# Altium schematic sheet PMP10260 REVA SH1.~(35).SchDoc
size 431 x 279 mm; Date: Not shown in title block; ApprovedBy: Not shown in title block; CheckedBy: Not shown in title block; Author: Not shown in title block; CompanyName: Not shown in title block; Engineer: Not shown in title block; Organization: Not shown in title block; Address1: Not shown in title block; Address2: Not shown in title block; Address3: Not shown in title block; Address4: Not shown in title block; DocumentNumber: 1; Revision: Use project parameter SCH_Rev; SheetNumber: 1; SheetTotal: 4; PageSetup: Record=PageOptions|CenterHorizontal=True|CenterVertical=True|PrintScale=1.00|XCorrection=1.00|YCorrection=1.00|PrintKind=0|BorderSize=5000000|LeftOffset=0|BottomOffset=0|Orientation=2|PaperLength=1000|PaperWidth=1000|Scale=100|PaperSource=15|PrintQuality=600|MediaType=1|DitherType=10|PaperKind=Letter|PrintScaleMode=1
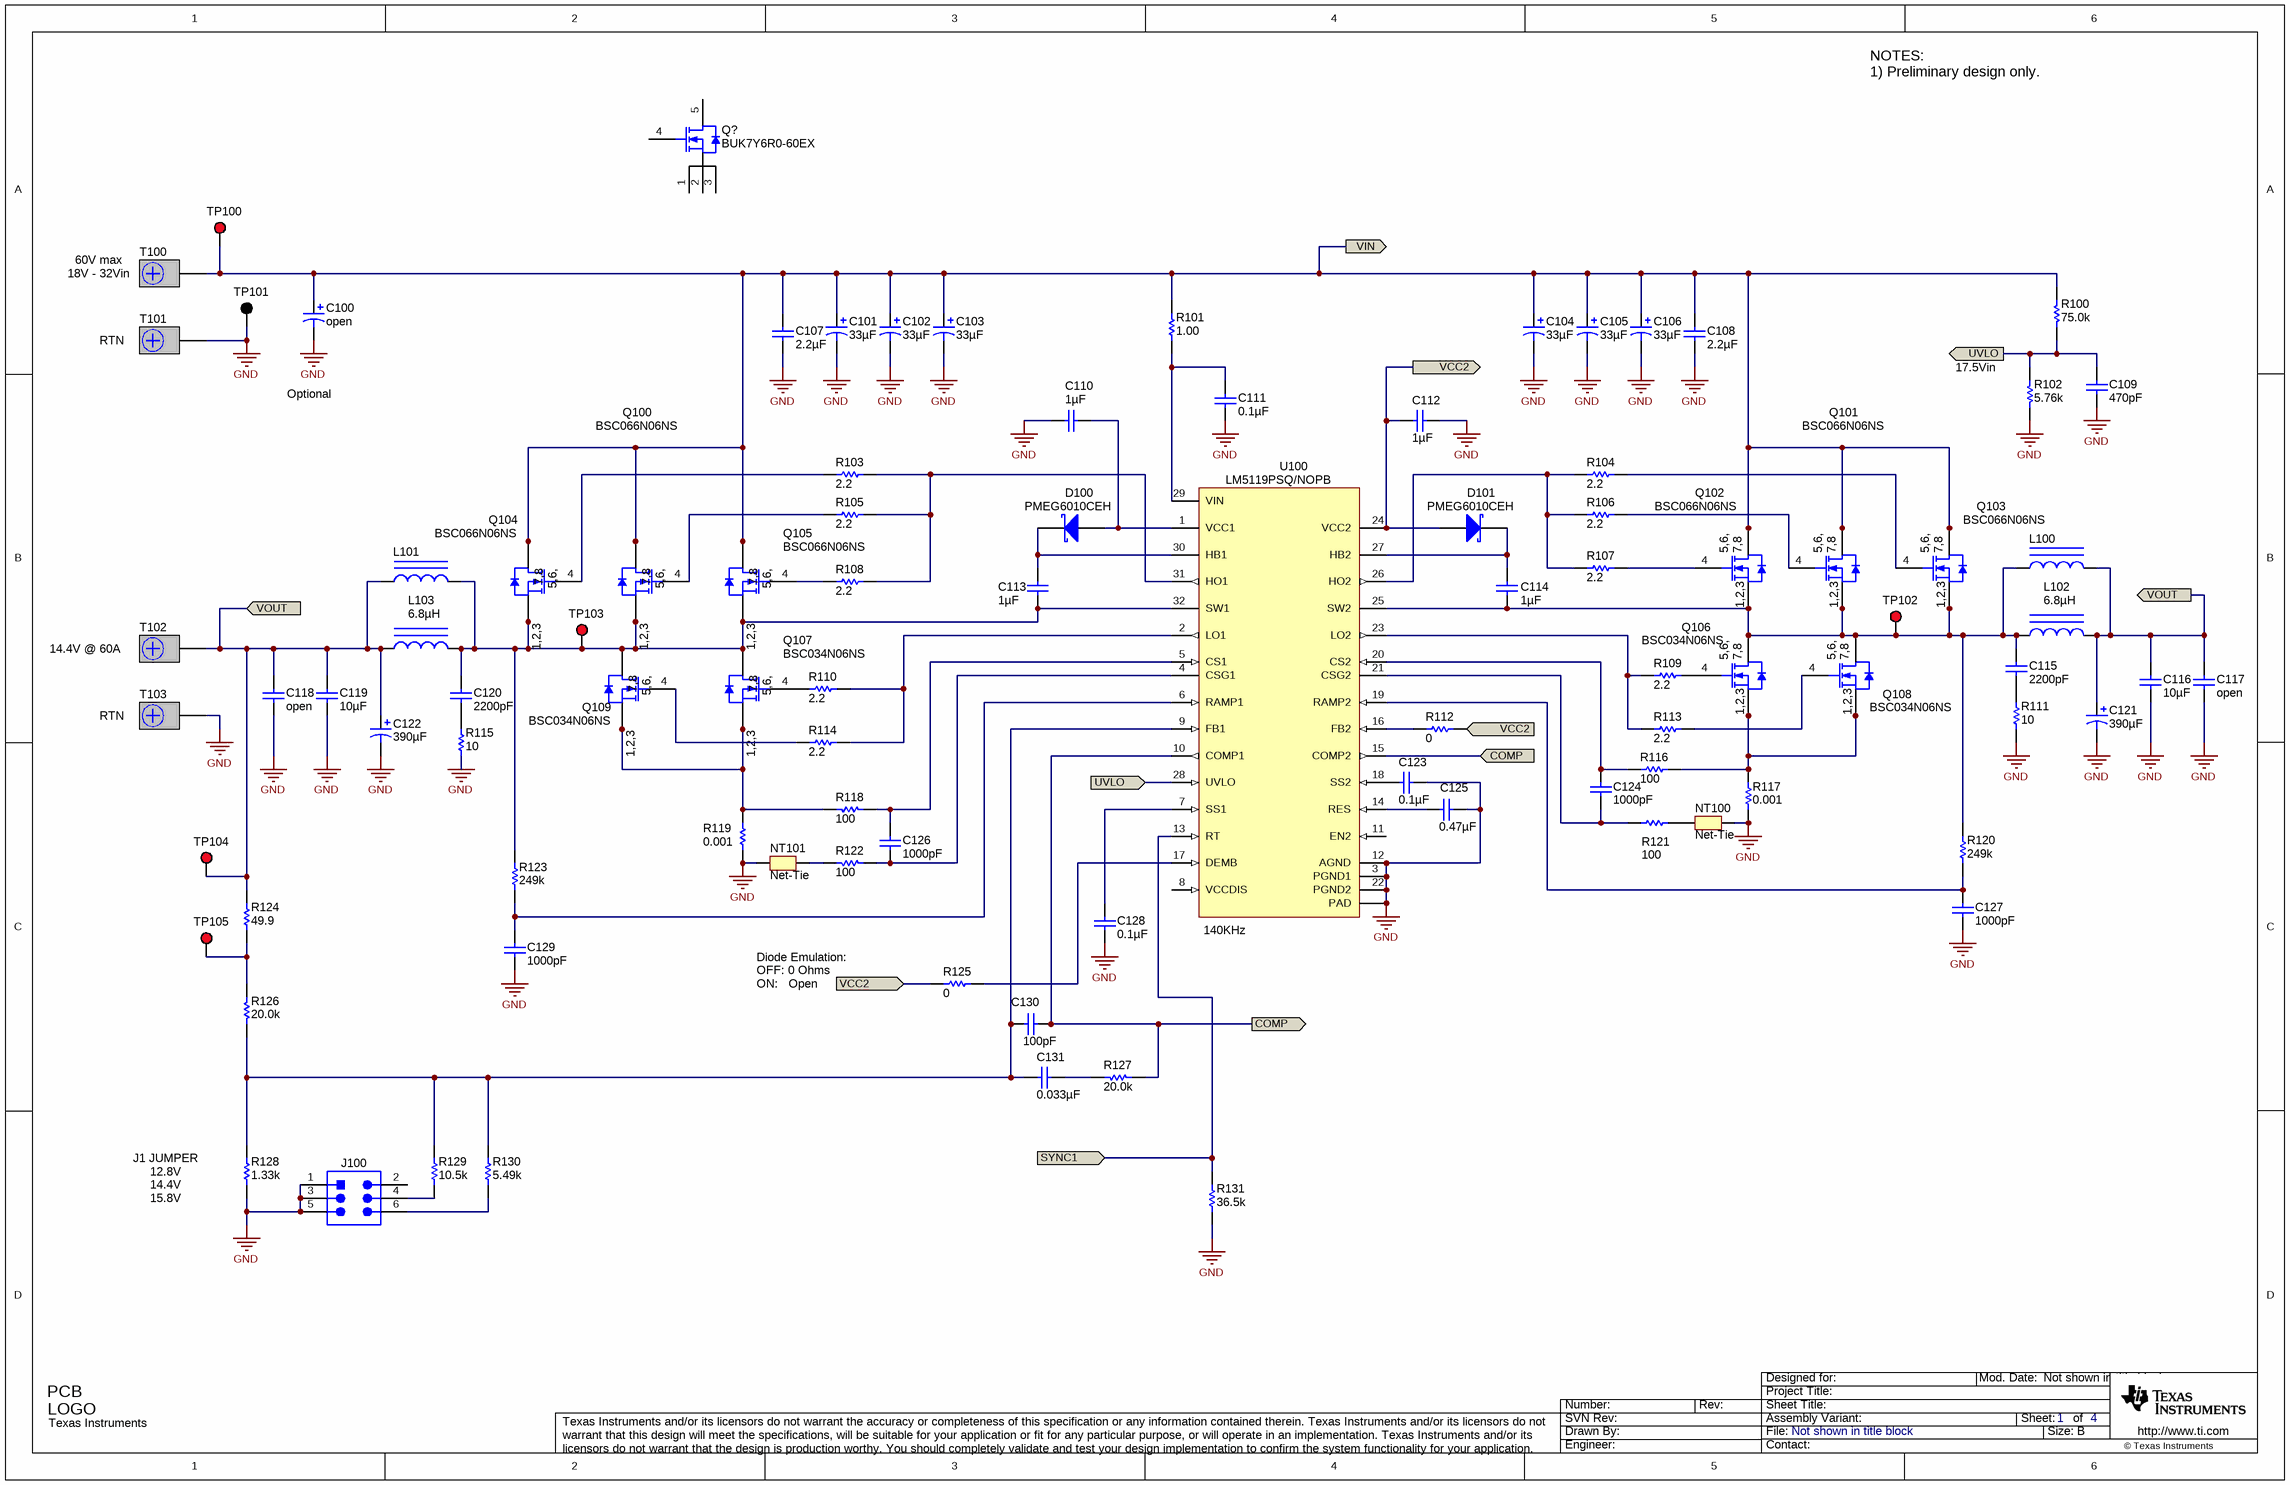
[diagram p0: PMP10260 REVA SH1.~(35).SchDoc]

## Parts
C100  ValueDisplayed: open  [SM_RADIAL_8MM]
C101  ValueDisplayed: 33µF  [SXV_E12]  (hidden comment: 63SXV33M)
C102  ValueDisplayed: 33µF  [SXV_E12]  (hidden comment: 63SXV33M)
C103  ValueDisplayed: 33µF  [SXV_E12]  (hidden comment: 63SXV33M)
C104  ValueDisplayed: 33µF  [SXV_E12]  (hidden comment: 63SXV33M)
C105  ValueDisplayed: 33µF  [SXV_E12]  (hidden comment: 63SXV33M)
C106  ValueDisplayed: 33µF  [SXV_E12]  (hidden comment: 63SXV33M)
C107  ValueDisplayed: 2.2µF  [1210]  (hidden comment: GRM32ER72A225KA35L)
C108  ValueDisplayed: 2.2µF  [1210]  (hidden comment: GRM32ER72A225KA35L)
C109  ValueDisplayed: 470pF  [0603]  (hidden comment: C1608C0G1H471J)
C110  ValueDisplayed: 1µF  [0603L]  (hidden comment: C1608X7R1E105K080AB)
C111  ValueDisplayed: 0.1µF  [0805_HV]  (hidden comment: C2012X7R2A104K)
C112  ValueDisplayed: 1µF  [0603L]  (hidden comment: C1608X7R1E105K080AB)
C113  ValueDisplayed: 1µF  [0603L]  (hidden comment: C1608X7R1E105K080AB)
C114  ValueDisplayed: 1µF  [0603L]  (hidden comment: C1608X7R1E105K080AB)
C115  ValueDisplayed: 2200pF  [0603L]  (hidden comment: C0603C222K5RAC)
C116  ValueDisplayed: 10µF  [1210L]  (hidden comment: GMK325AB7106MM-T)
C117  ValueDisplayed: open  [1210]
C118  ValueDisplayed: open  [1210]
C119  ValueDisplayed: 10µF  [1210L]  (hidden comment: GMK325AB7106MM-T)
C120  ValueDisplayed: 2200pF  [0603L]  (hidden comment: C0603C222K5RAC)
C121  ValueDisplayed: 390µF  [SM_RADIAL_8MM]  (hidden comment: 20SVPF390M)
C122  ValueDisplayed: 390µF  [SM_RADIAL_8MM]  (hidden comment: 20SVPF390M)
C123  ValueDisplayed: 0.1µF  [0603L]  (hidden comment: C1608X7R1H104K)
C124  ValueDisplayed: 1000pF  [0603]  (hidden comment: C1608C0G1H102J)
C125  ValueDisplayed: 0.47µF  [0603L]  (hidden comment: C0603C474K4RACTU)
C126  ValueDisplayed: 1000pF  [0603]  (hidden comment: C1608C0G1H102J)
C127  ValueDisplayed: 1000pF  [0603]  (hidden comment: C1608C0G1H102J)
C128  ValueDisplayed: 0.1µF  [0603L]  (hidden comment: C1608X7R1H104K)
C129  ValueDisplayed: 1000pF  [0603]  (hidden comment: C1608C0G1H102J)
C130  ValueDisplayed: 100pF  [0603]  (hidden comment: C1608C0G1H101J)
C131  ValueDisplayed: 0.033µF  [0603]  (hidden comment: GRM188R71H333KA61D)
D100  PMEG6010CEH  [SOD-123F]
D101  PMEG6010CEH  [SOD-123F]
J100  PEC03DAAN  [SULLINS_PEC03DAAN]  (value not drawn)
L100  (no value)  [XAL1510]
L101  (no value)  [XAL1510]
L102  ValueDisplayed: 6.8µH  [SER2915]  (hidden comment: SER2915H-682KL)
L103  ValueDisplayed: 6.8µH  [SER2915]  (hidden comment: SER2915H-682KL)
Logo100  Texas Instruments  [TI_Stacked_Overlay_Small]  (no BOM)
NT100  Net-Tie  [Net-Tie_10mil]  (net tie, no BOM)
NT101  Net-Tie  [Net-Tie_10mil]  (net tie, no BOM)
Q100  BSC066N06NS  [PG-TDSON-8]
Q101  BSC066N06NS  [PG-TDSON-8]
Q102  BSC066N06NS  [PG-TDSON-8]
Q103  BSC066N06NS  [PG-TDSON-8]
Q104  BSC066N06NS  [PG-TDSON-8]
Q105  BSC066N06NS  [PG-TDSON-8]
Q106  BSC034N06NS  [PG-TDSON-8]
Q107  BSC034N06NS  [PG-TDSON-8]
Q108  BSC034N06NS  [PG-TDSON-8]
Q109  BSC034N06NS  [PG-TDSON-8]
Q?  BUK7Y6R0-60EX  [LFPAK56]
R100  value 75.0k  [0603]  (hidden comment: CRCW060375K0FKEA)
R101  value 1.00  [0805_HV]  (hidden comment: CRCW08051R00FKEA)
R102  value 5.76k  [0603]  (hidden comment: CRCW06035K76FKEA)
R103  value 2.2  [0603L]  (hidden comment: CRCW06032R20JNEA)
R104  value 2.2  [0603L]  (hidden comment: CRCW06032R20JNEA)
R105  value 2.2  [0603L]  (hidden comment: CRCW06032R20JNEA)
R106  value 2.2  [0603L]  (hidden comment: CRCW06032R20JNEA)
R107  value 2.2  [0603L]  (hidden comment: CRCW06032R20JNEA)
R108  value 2.2  [0603L]  (hidden comment: CRCW06032R20JNEA)
R109  value 2.2  [0603L]  (hidden comment: CRCW06032R20JNEA)
R110  value 2.2  [0603L]  (hidden comment: CRCW06032R20JNEA)
R111  value 10  [2010M]  (hidden comment: CRCW201010R0JNEFHP)
R112  value 0  [0603L]  (hidden comment: CRCW06030000Z0EA)
R113  value 2.2  [0603L]  (hidden comment: CRCW06032R20JNEA)
R114  value 2.2  [0603L]  (hidden comment: CRCW06032R20JNEA)
R115  value 10  [2010M]  (hidden comment: CRCW201010R0JNEFHP)
R116  value 100  [0603L]  (hidden comment: RC0603FR-07100RL)
R117  value 0.001  [2512M]  (hidden comment: ERJ-M1WTF1M0U)
R118  value 100  [0603L]  (hidden comment: RC0603FR-07100RL)
R119  value 0.001  [2512M]  (hidden comment: ERJ-M1WTF1M0U)
R120  value 249k  [0603]  (hidden comment: CRCW0603249KFKEA)
R121  value 100  [0603L]  (hidden comment: RC0603FR-07100RL)
R122  value 100  [0603L]  (hidden comment: RC0603FR-07100RL)
R123  value 249k  [0603]  (hidden comment: CRCW0603249KFKEA)
R124  value 49.9  [0603]  (hidden comment: CRCW060349R9FKEA)
R125  value 0  [0603L]  (hidden comment: CRCW06030000Z0EA)
R126  value 20.0k  [0603L]  (hidden comment: CRCW060320K0FKEA)
R127  value 20.0k  [0603]  (hidden comment: CRCW060320K0FKEA)
R128  value 1.33k  [0603]  (hidden comment: CRCW06031K33FKEA)
R129  value 10.5k  [0603]  (hidden comment: CRCW060310K5FKEA)
R130  value 5.49k  [0603]  (hidden comment: CRCW06035K49FKEA)
R131  value 36.5k  [0603]  (hidden comment: CRCW060336K5FKEA)
T100  CB35-36-CY  [CB35-36-CY]  (value not drawn)
T101  CB35-36-CY  [CB35-36-CY]  (value not drawn)
T102  CB70-14-CY  [CB70-14-CY]  (value not drawn)
T103  CB70-14-CY  [CB70-14-CY]  (value not drawn)
TP100  5010  [Keystone5010]  (value not drawn)
TP101  5011  [Keystone5011]  (value not drawn)
TP102  5010  [Keystone5010]  (value not drawn)
TP103  5010  [Keystone5010]  (value not drawn)
TP104  5010  [Keystone5010]  (value not drawn)
TP105  5010  [Keystone5010]  (value not drawn)
U100  LM5119PSQ/NOPB  [RTV0032A]

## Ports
COMP, SYNC1, UVLO, VCC2, VIN, VOUT

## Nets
GND: C100.2(-) C101.2(-) C102.2(-) C103.2(-) C104.2(-) C105.2(-) C106.2(-) C107.2 C108.2 C109.2 C110.2 C111.2 C112.2 C116.2 C117.2 C118.2 C119.2 C121.2(-) C122.2(-) C123.1 C125.1 C127.2 C128.2 C129.2 J100.1 J100.3 J100.5 NT100.2 NT101.1 R102.1 R111.1 R115.1 R117.1 R119.1 R128.1 R131.1 T101.1 T103.1 TP101.1 U100.3(PGND1) U100.12(AGND) U100.22(PGND2) U100.33(PAD)
COMP: C130.1 R127.1 U100.10(COMP1) U100.15(COMP2) ; port COMP
SYNC1: R131.2 U100.13(RT) ; port SYNC1
UVLO: C109.1 R100.1 R102.2 U100.28(UVLO) ; port UVLO
VCC2: C112.1 D101.2(A) R112.2 R125.1 U100.24(VCC2) ; port VCC2
VIN: C100.1(+) C101.1(+) C102.1(+) C103.1(+) C104.1(+) C105.1(+) C106.1(+) C107.1 C108.1 Q100.5(D) Q100.6(D) Q100.7(D) Q100.8(D) Q100.9(D) Q101.5(D) Q101.6(D) Q101.7(D) Q101.8(D) Q101.9(D) Q102.5(D) Q102.6(D) Q102.7(D) Q102.8(D) Q102.9(D) Q103.5(D) Q103.6(D) Q103.7(D) Q103.8(D) Q103.9(D) Q104.5(D) Q104.6(D) Q104.7(D) Q104.8(D) Q104.9(D) Q105.5(D) Q105.6(D) Q105.7(D) Q105.8(D) Q105.9(D) R100.2 R101.1 T100.1 TP100.1 ; port VIN
VOUT: C116.1 C117.1 C118.1 C119.1 C121.1(+) C122.1(+) L100.2 L101.1 L102.2 L103.1 R124.2 T102.1 TP104.1 ; port VOUT
NetC110_1: C110.1 D100.2(A) U100.1(VCC1)
NetC111_1: C111.1 R101.2 U100.29(VIN)
NetC113_1: C113.1 D100.1(K) U100.30(HB1)
NetC113_2: C113.2 C120.1 L101.2 L103.2 Q100.1(S) Q100.2(S) Q100.3(S) Q104.1(S) Q104.2(S) Q104.3(S) Q105.1(S) Q105.2(S) Q105.3(S) Q107.5(D) Q107.6(D) Q107.7(D) Q107.8(D) Q107.9(D) Q109.5(D) Q109.6(D) Q109.7(D) Q109.8(D) Q109.9(D) R123.2 TP103.1 U100.32(SW1)
NetC114_1: C114.1 D101.1(K) U100.27(HB2)
NetC114_2: C114.2 C115.1 L100.1 L102.1 Q101.1(S) Q101.2(S) Q101.3(S) Q102.1(S) Q102.2(S) Q102.3(S) Q103.1(S) Q103.2(S) Q103.3(S) Q106.5(D) Q106.6(D) Q106.7(D) Q106.8(D) Q106.9(D) Q108.5(D) Q108.6(D) Q108.7(D) Q108.8(D) Q108.9(D) R120.2 TP102.1 U100.25(SW2)
NetC115_2: C115.2 R111.2
NetC120_2: C120.2 R115.2
NetC123_2: C123.2 U100.18(SS2)
NetC124_1: C124.1 R116.1 U100.20(CS2)
NetC124_2: C124.2 R121.1 U100.21(CSG2)
NetC125_2: C125.2 U100.14(RES)
NetC126_1: C126.1 R118.1 U100.5(CS1)
NetC126_2: C126.2 R122.1 U100.4(CSG1)
NetC127_1: C127.1 R120.1 U100.19(RAMP2)
NetC128_1: C128.1 U100.7(SS1)
NetC129_1: C129.1 R123.1 U100.6(RAMP1)
NetC130_2: C130.2 C131.2 R126.1 R128.2 R129.2 R130.2 U100.9(FB1)
NetC131_1: C131.1 R127.2
NetJ100_4: J100.4 R129.1
NetJ100_6: J100.6 R130.1
NetNT100_1: NT100.1 R121.2
NetNT101_2: NT101.2 R122.2
NetQ100_4: Q100.4(G) R105.1
NetQ101_4: Q101.4(G) R106.2
NetQ102_4: Q102.4(G) R107.2
NetQ103_4: Q103.4(G) R104.2
NetQ104_4: Q104.4(G) R103.1
NetQ105_4: Q105.4(G) R108.1
NetQ106_1: Q106.1(S) Q106.2(S) Q106.3(S) Q108.1(S) Q108.2(S) Q108.3(S) R116.2 R117.2
NetQ106_4: Q106.4(G) R109.2
NetQ107_1: Q107.1(S) Q107.2(S) Q107.3(S) Q109.1(S) Q109.2(S) Q109.3(S) R118.2 R119.2
NetQ107_4: Q107.4(G) R110.1
NetQ108_4: Q108.4(G) R113.2
NetQ109_4: Q109.4(G) R114.1
NetR103_2: R103.2 R105.2 R108.2 U100.31(HO1)
NetR104_1: R104.1 R106.1 R107.1 U100.26(HO2)
NetR109_1: R109.1 R113.1 U100.23(LO2)
NetR110_2: R110.2 R114.2 U100.2(LO1)
NetR112_1: R112.1 U100.16(FB2)
NetR124_1: R124.1 R126.2 TP105.1
NetR125_2: R125.2 U100.17(DEMB)

Not connected (* = marked no-connect by the designer): J100 2; Q? 1(S) 2(S) 3(S) 4(G) 5(D); U100 8(VCCDIS) 11(EN2)

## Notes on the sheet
- NOTES:
  1) Preliminary design only.
- (near T100) 18V - 32Vin
- 60V max
- RTN
- (near R102) 17.5Vin
- Optional
- 14.4V @ 60A
- Diode Emulation:
- OFF: 0 Ohms
- (near U100) 140KHz
- ON:   Open
- 12.8V
- (near R128) J1 JUMPER
- 14.4V
- 15.8V

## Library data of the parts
C100 = 20SVP100M: CAP, OS-CON, open; Manufacturer: Sanyo; Polarized: Y; CompType: Capacitor; Value: 82uF; U/M: EA; Cap_F: 0.0001; Tolerance_%: 20; Value1: 0.020 ohm; VDC_V: 35; Value2: 35V; ESR_Ohm: 0.024; IRMS_A: 3.32; TaMin_C: -55; TaMax_C: 105; Cap_Case: 8.3x8.3x11.9
C101-C106 = 63SXV33M: CAP, OS-CON, 33uF, 63V, +/-20%, 0.025 ohm, 8.0x11.9mm SMD; Manufacturer: Panasonic; Polarized: Y; CompType: Capacitor; U/M: EA; Cap_F: 0.000033; Tolerance_%: 20; VDC_V: 63; ESR_Ohm: 0.025; IRMS_A: 2.95; TaMin_C: -55; TaMax_C: 105
C107 C108 = GRM32ER72A225KA35L: CAP, CERM, 2.2uF, 100V, +/-10%, X7R, 1210; Manufacturer: MuRata; Polarized: N; CompType: Capacitor; U/M: EA; Cap_F: 0.0000022; Tolerance_%: 10; ESR_Ohm: 0.007; Value1: 0.007 ohm; VDC_V: 100; IRMS_A: 4.4; TaMin_C: -55; TaMax_C: 125
C109 = C1608C0G1H471J: CAP, CERM, 470pF, 50V, +/-5%, C0G/NP0, 0603; Manufacturer: TDK; Polarized: N; CompType: Capacitor; U/M: EA; Cap_F: 0.00000000047; Tolerance_%: 5; ESR_Ohm: 0.0922; Value1: 0.0922 ohm; VDC_V: 50; TaMin_C: -55; TaMax_C: 125
C110 C112-C114 = C1608X7R1E105K080AB: CAP, CERM, 1uF, 25V, +/-10%, X7R, 0603; Manufacturer: TDK; Polarized: N; CompType: Capacitor; U/M: EA; Cap_F: 0.000001; Tolerance_%: 10; Value1: Unknown; VDC_V: 25; TaMin_C: -55; TaMax_C: 125; Cap_Case: 0603
C111 = C2012X7R2A104K: CAP, CERM, 0.1uF, 100V, +/-10%, X7R, 0805; Manufacturer: TDK; Polarized: N; CompType: Capacitor; U/M: EA; Cap_F: 0.0000001; Tolerance_%: 10; ESR_Ohm: 0.0158; Value1: 0.0158 ohm; VDC_V: 100; TaMin_C: -55; TaMax_C: 125; Cap_Case: 0805
C115 C120 = C0603C222K5RAC: CAP, CERM, 2200pF, 50V, +/-10%, X7R, 0603; Manufacturer: Kemet; Polarized: N; CompType: Capacitor; U/M: EA; Cap_F: 0.0000000022; Tolerance_%: 10; Value1: Unknown; VDC_V: 50; TaMin_C: -55; TaMax_C: 125; Cap_Case: 0603
C116 C119 = GMK325AB7106MM-T: CAP, CERM, 10uF, 35V, +/-20%, X7R, 1206; Manufacturer: Taiyo Yuden; Polarized: N; CompType: Capacitor; U/M: EA; Cap_F: 0.00001; Tolerance_%: 20; Value1: Unknown; VDC_V: 35; TaMin_C: -55; TaMax_C: 125; Cap_Case: 1210
C117 C118 = C3225X7R1H335M: CAP, CERM, open, 1210; Manufacturer: TDK; Polarized: N; CompType: Capacitor; Value: 10uF; U/M: EA; Cap_F: 0.0000033; Tolerance_%: 20; Value1: Unknown; VDC_V: 50; Value2: 50V; TempCo: X5R; TaMin_C: -55; TaMax_C: 125
C121 C122 = 20SVP100M: CAP, OS-CON, 390uF, 20V, +/-20%, 0.014 ohm, 8x10 SMD; Manufacturer: Sanyo; Polarized: Y; CompType: Capacitor; U/M: EA; Cap_F: 0.0001; Tolerance_%: 20; ESR_Ohm: 0.024; IRMS_A: 3.32; TaMin_C: -55; TaMax_C: 105; Cap_Case: 8.3x8.3x11.9
C123 C128 = C1608X7R1H104K: CAP, CERM, 0.1uF, 50V, +/-10%, X7R, 0603; Manufacturer: TDK; Polarized: N; CompType: Capacitor; U/M: EA; Cap_F: 0.0000001; Tolerance_%: 10; ESR_Ohm: 0.017; Value1: 0.017 ohm; VDC_V: 50; TaMin_C: -55; TaMax_C: 125; Cap_Case: 0603
C124 C126 C127 C129 = C1608C0G1H102J: CAP, CERM, 1000pF, 50V, +/-5%, C0G/NP0, 0603; Manufacturer: TDK; Polarized: N; CompType: Capacitor; U/M: EA; Cap_F: 0.000000001; Tolerance_%: 5; ESR_Ohm: 0.0563; Value1: 0.0563 ohm; VDC_V: 50; TaMin_C: -55; TaMax_C: 125
C125 = C0603C474K4RACTU: CAP, CERM, 0.47uF, 16V, +/-10%, X7R, 0603; Manufacturer: Kemet; Polarized: N; CompType: Capacitor; U/M: EA; Cap_F: 0.00000047; Tolerance_%: 10; Value1: Unknown; VDC_V: 16; TaMin_C: -55; TaMax_C: 125; Cap_Case: 0603
C130 = C1608C0G1H101J: CAP, CERM, 100pF, 50V, +/-5%, C0G/NP0, 0603; Manufacturer: TDK; Polarized: N; CompType: Capacitor; U/M: EA; Cap_F: 0.0000000001; Tolerance_%: 5; ESR_Ohm: 0.1679; Value1: 0.1679 ohm; VDC_V: 50; TaMin_C: -55; TaMax_C: 125
C131 = GRM188R71H333KA61D: CAP, CERM, 0.033uF, 50V, +/-10%, X7R, 0603; Manufacturer: MuRata; Polarized: N; CompType: Capacitor; U/M: EA; Cap_F: 0.000000033; Tolerance_%: 10; Value1: Unknown; VDC_V: 50; TaMin_C: -55; TaMax_C: 125
D100 D101 = PMEG6010CEH,115: Diode, Schottky, 60V, 1A, SOD-123F; Manufacturer: NXP Semiconductor; U/M: EA; Vf_V: 0.57; Value2: 0.57V; Io_A: 1; Vr_V: 60; TJmax_C: 150
J100 = PEC03DAAN: Header, 100mil, 3x2, Tin, TH; Manufacturer: Sullins Connector Solutions; SymbolCreator: a0412235; U/M: EA
L100 L101 = XAL1510-682MEB: Inductor, Shielded, Composite, 6.8uH, 26A, 0.00417 ohm, SMD; Ind_H: 6.8E-6; Imax_A: 26; Irms: 26A @ 40C rise; Isat: 36A @ 30% inductance drop; U/M: EA
L102 L103 = SER2915H-682KL: Inductor, Shielded E Core, Ferrite, 6.8uH, 30A, 0.00186 ohm, SMD; Manufacturer: Coilcraft; Ind_H: 6.8E-6; Imax_A: 30; Irms: 30A @ 40C rise; Isat: 36.2A @ 30% inductance drop; U/M: EA
Logo100 = TI_Logo: Texas Instrument Corporate Signature; SymbolCreator: codlsc
NT100 NT101 = Net-Tie: Single point connection between nets.; SymbolCreator: codlsc
Q100-Q105 = BSC067N06LS3 G: MOSFET, N-CH, 60V, 0.0066 ohm, 17nC, PG-TDSON-8; Manufacturer: Infineon Technologies; Alternate Manufacturer: None; U/M: EA; ChType: N; VdsMax_V: 60; Rdson45_Ohm: 0.0121; Value2: 21 nC; QgTyp_nC: 23; Vgs_V: 20; IdsMax_A: 50
Q106-Q109 = BSC067N06LS3 G: MOSFET, N-CH, 60V, 0.0034 ohm, 33nC, PG-TDSON-8; Manufacturer: Infineon Technologies; Alternate Manufacturer: None; U/M: EA; ChType: N; VdsMax_V: 60; Rdson45_Ohm: 0.0121; QgTyp_nC: 23; Vgs_V: 20; IdsMax_A: 50
Q? = BUK7Y6R0-60EX: MOSFET, N-CH, 60V, 100A, SOT669; Manufacturer: NXP Semiconductor; Alternate Manufacturer: None; SymbolCreator: a0412235; U/M: EA; ChType: N; VdsMax_V: 60; Value1: ? ohm; Value2: 45.4 nC; QgTyp_nC: 45.4; Vgs_V: 20; IdsMax_A: 100
R100 = CRCW060375K0FKEA: RES, 75.0k ohm, 1%, 0.1W, 0603; Manufacturer: Vishay-Dale; CompType: Resistor; Res_ohm: 75000; Value_Code: 75k0; Tolerance_%: 1; Power_W: 0.1; VDC_V: 75; TempCo: 100 ppm/C; EIA_Code: E96; U/M: EA
R101 = CRCW08051R00FKEA: RES, 1.00 ohm, 1%, 0.125W, 0805; Manufacturer: Vishay-Dale; CompType: Resistor; Res_ohm: 1; Value_Code: 1R00; Power_W: 0.125; VDC_V: 150; TempCo: 100 ppm/C; EIA_Code: E96; U/M: EA
R102 = CRCW06035K76FKEA: RES, 5.76k ohm, 1%, 0.1W, 0603; Manufacturer: Vishay-Dale; CompType: Resistor; Res_ohm: 5760; Value_Code: 5k76; Tolerance_%: 1; Power_W: 0.1; VDC_V: 75; TempCo: 100 ppm/C; EIA_Code: E96; U/M: EA
R103-R110 R113 R114 = CRCW06032R20JNEA: RES, 2.2 ohm, 5%, 0.1W, 0603; Manufacturer: Vishay-Dale; CompType: Resistor; Value_Code: 2R20; Tolerance_%: 5; Power_W: 0.1; VDC_V: 75; TempCo: 200 ppm/C; EIA_Code: E24; U/M: EA
R111 R115 = CRCW20101R00JNEFHP: RES, 10 ohm, 5%, 1W, 2010; Manufacturer: Vishay-Dale; CompType: Resistor; Res_ohm: 1; Value_Code: 1R00; Tolerance_%: 5; VDC_V: 400; TempCo: 200 ppm/C; EIA_Code: E24; U/M: EA
R112 R125 = CRCW06030000Z0EA: RES, 0 ohm, 5%, 0.1W, 0603; Manufacturer: Vishay-Dale; CompType: Resistor; Value_Code: 0000; Tolerance_%: 5; Power_W: 0.1; VDC_V: 75; TempCo: 200 ppm/C; EIA_Code: E24; U/M: EA
R116 R118 R121 R122 = RC0603FR-07100RL: RES, 100 ohm, 1%, 0.1W, 0603; Manufacturer: Yageo America; CompType: Resistor; Value_Code: 100R; Tolerance_%: 1; Power_W: 0.1; VDC_V: 150; TempCo: 200 ppm/C; EIA_Code: E96; U/M: EA
R117 R119 = ERJ-M1WTF1M0U: RES, 0.001 ohm, 1%, 1W, 2512; Manufacturer: Panasonic; CompType: Resistor; Value_Code: R001; Tolerance_%: 1; TempCo: ppm/C; EIA_Code: E96; U/M: EA
R120 R123 = CRCW0603249KFKEA: RES, 249k ohm, 1%, 0.1W, 0603; Manufacturer: Vishay-Dale; CompType: Resistor; Res_ohm: 249000; Tolerance_%: 1; Power_W: 0.1; VDC_V: 75; TempCo: 100 ppm/C; EIA_Code: E96; U/M: EA
R124 = CRCW060349R9FKEA: RES, 49.9 ohm, 1%, 0.1W, 0603; Manufacturer: Vishay-Dale; CompType: Resistor; Value_Code: 49R9; Tolerance_%: 1; Power_W: 0.1; VDC_V: 75; TempCo: 100 ppm/C; EIA_Code: E96; U/M: EA
R126 R127 = CRCW060320K0FKEA: RES, 20.0k ohm, 1%, 0.1W, 0603; Manufacturer: Vishay-Dale; CompType: Resistor; Res_ohm: 20000; Value_Code: 20k0; Tolerance_%: 1; Power_W: 0.1; VDC_V: 75; TempCo: 100 ppm/C; EIA_Code: E96; U/M: EA
R128 = CRCW06031K33FKEA: RES, 1.33k ohm, 1%, 0.1W, 0603; Manufacturer: Vishay-Dale; CompType: Resistor; Res_ohm: 1330; Value_Code: 1k33; Tolerance_%: 1; Power_W: 0.1; VDC_V: 75; TempCo: 100 ppm/C; EIA_Code: E96; U/M: EA
R129 = CRCW060310K5FKEA: RES, 10.5k ohm, 1%, 0.1W, 0603; Manufacturer: Vishay-Dale; CompType: Resistor; Res_ohm: 10500; Value_Code: 10k5; Tolerance_%: 1; Power_W: 0.1; VDC_V: 75; TempCo: 100 ppm/C; EIA_Code: E96; U/M: EA
R130 = CRCW06035K49FKEA: RES, 5.49k ohm, 1%, 0.1W, 0603; Manufacturer: Vishay-Dale; CompType: Resistor; Res_ohm: 5490; Value_Code: 5k49; Tolerance_%: 1; Power_W: 0.1; VDC_V: 75; TempCo: 100 ppm/C; EIA_Code: E96; U/M: EA
R131 = CRCW060336K5FKEA: RES, 36.5k ohm, 1%, 0.1W, 0603; Manufacturer: Vishay-Dale; CompType: Resistor; Res_ohm: 36500; Value_Code: 36k5; Tolerance_%: 1; Power_W: 0.1; VDC_V: 75; TempCo: 100 ppm/C; EIA_Code: E96; U/M: EA
T100 T101 = CB35-36-CY: Terminal 50A Lug; Manufacturer: Panduit; SymbolCreator: crossc; CompType: Screw Terminal; U/M: EA
T102 T103 = CB70-14-CY: Terminal 90A Lug; Manufacturer: Panduit; SymbolCreator: crossc; CompType: Screw Terminal; U/M: EA
TP100 TP102-TP105 = 5010: Test Point, Multipurpose, Red, TH; Manufacturer: Keystone; CompType: Test Point Loop; U/M: EA
TP101 = 5011: Test Point, Multipurpose, Black, TH; Manufacturer: Keystone; CompType: Test Point Loop; U/M: EA
U100 = LM5119PSQ/NOPB: LM5119/LM5119Q Wide Input Range Dual Synchronous Buck Controller, RTV0032A; Alternate Manufacturer: None; Manufacturer: Texas Instruments; SymbolCreator: a0411947; CompType: IC; U/M: EA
